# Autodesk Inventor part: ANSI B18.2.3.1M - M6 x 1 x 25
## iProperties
Comments: To add or edit properties for Autodesk Inventor files, use iProperties.
Created: 2005-06
Part Number: ANSI B18.2.3.1M - M6 x 1 x 25
Vendor: Autodesk Inc.
Document SubType Name: Modeling
Designer: John Blackburn
Material: Default
Description: Metric Hex Cap Screw
Standard: ANSI B18.2.3.1M
Alert: To add or edit properties for Autodesk Inventor files, use iProperties.
Control State: 0
Master: False
Checked Out: False
Shininess: 64.0
Length Units: 11269
Angle Units: 11279
Time Units: 11290
Mass Units: 11283
Length Display Precision: 3
Angle Display Precision: 2
Compacted: True
EGR: 1
Classification: un/spsc 31161513
Density: 0.0
Volumn: 0.0
Area: 0.0
PropertySet Name: Model Information
Author: John Blackburn
Revision Number: 8
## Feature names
1. Body [Revolution]
2. Head [Extrusion]
3. Chamfer1 [Revolution]
4. Chamfer2
